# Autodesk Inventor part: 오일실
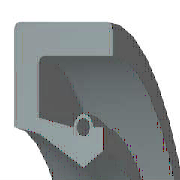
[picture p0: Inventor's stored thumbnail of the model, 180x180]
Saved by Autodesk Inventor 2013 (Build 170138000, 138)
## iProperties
IsCustomPart: 1
Created: 2015-10
Part Number: 오일실
Material: 고무
Description: 오일-실
Document SubType Name: Modeling
Standard: KS B 2804
Designer: mdu
Standards Organization: KS
Language: ko-KR
Size Designation: S - 25 38 8
Categories: <MemberInstance><Categories><Category DisplayName="샤프트 부품" InternalName="7f7aeb1f-a693-4053-b835-cee3144e0d98" Mnemonic="SHFT"><Category DisplayName="실링" Intern
Density: 0.93 g/cm^3
Mass: 2.23721 g
Surface Area: 37.0166 cm^2
Volume: 2.4056 cm^3
Author: mdu
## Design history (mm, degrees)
revolve "본체" stored, may be unused: angle "d17" = 90 deg
revolve "스프링1" stored, may be unused: angle "d18" = 90 deg
body "Solid1"
sketch "스케치1"
  geometry: L1 (0, 19)-(8, 19); L2 (8, 19)-(8, 17.75); L3 (8, 17.75)-(1.75, 17.75); L4 (0, 19)-(0, 14.6); L5 (0, 14.6)-(1.75, 14.25); L6 (1.75, 14.25)-(4.9, 12.5); L7 (4.9, 12.5)-(0, 12.5); L8 (6.3, 13.375)-(6.3, 14.6); L9 (0, 0)-(9.586, 0) reference; L10 (4.9, 12.5)-(6.3, 13.375); L11 (0, 18)-(0, -3) reference; L12 (-1.917, 0)-(11.503, 0) reference; L13 (4.2, 14.6)-(1.75, 15.09); L14 (1.75, 15.09)-(1.75, 17.75); L15 (6.3, 14.6)-(5.6, 14.6); C1 r 0.455 at (4.9, 14.6); A1 r 0.7 centre (4.9, 14.6) between (5.6, 14.6) and (4.2, 14.6)
  constraints: 26 end point, 5 horizontal alignment, 4 perpendicular, 2 centre point, 2 collinear, 2 horizontal, 2 parallel, 2 point on circle, 2 point on line, 2 vertical alignment, 1 coincident
  dimensions: "d0" = 38 diameter of L1 L9 (= SD2); "d1" = 26.75 diameter of L8.start L9 (= ABDM); "d2" = 1.25 distance of L1.end L2.end (computed from SD); "d3" = 0.91 diameter of C1 (= SPDI); "d4" = 1.4 diameter of A1 (= SPDA); "d5" = 25 diameter of L6.end L9 (= NND); "d6" = 28.5 diameter of L5.end L9 (= TKDM); "d7" = 29.2 diameter of L4.end L9 (= HLDM); "d8" = 4.9 distance from line of C1.centre L4 (= SPDST); "d9" = 6.3 distance between parallel lines of L8 L4 (= SDI); "d10" = 8 distance between parallel lines of L2 L4 (= SWDT); "d12" = 1.75 distance between parallel lines of L14 L4 (= SD)
fillet "모깎기1" dims "d11" = 0.3 (= RR)
other parameters: "SD2" = 38 [user parameter; used in 1 equation term], "SWDT" = 8 [user parameter; used in 1 equation term], "RR" = 0.3 [user parameter; used in 1 equation term], "SD" = 1.75 [user parameter; used in 2 equation terms], "NND" = 25 [user parameter; used in 1 equation term], "SPDA" = 1.4 [user parameter; used in 1 equation term], "SPDI" = 0.91 [user parameter; used in 1 equation term], "TKDM" = 28.5 [user parameter; used in 1 equation term], "HLDM" = 29.2 [user parameter; used in 1 equation term], "ABDM" = 26.75 [user parameter; used in 1 equation term], "SDI" = 6.3 [user parameter; used in 1 equation term], "SPDST" = 4.9 [user parameter; used in 1 equation term], "d13" = 0, "d14" = 0, "d15" = 0, "LAB" = 0.35 [user parameter]
